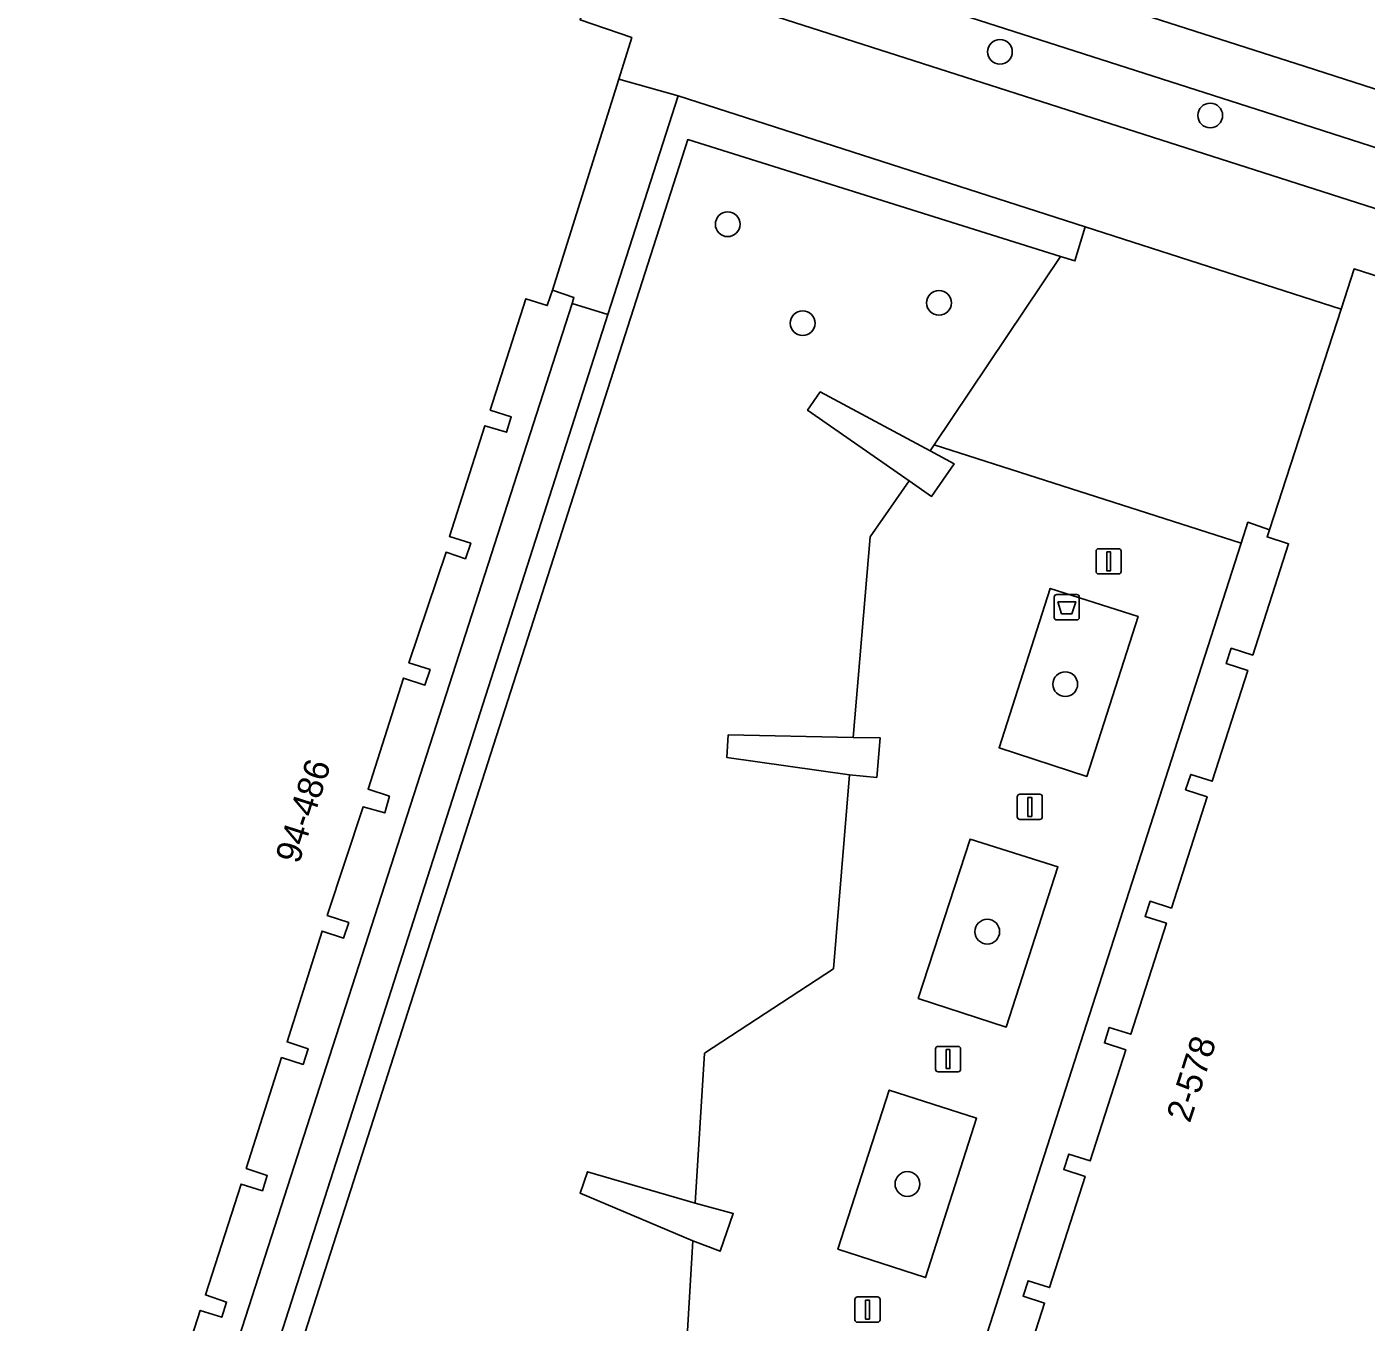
# Model space of a CAD drawing. Extents: x 160675 to 161153, y 383241 to 383714.
# Drawn here: x 160887.3 to 160940.2, y 383336.8 to 383388 of the extents above; entities that cross this region are included whole.
import ezdxf

# ---------------------------------------------------------------- set-up
doc = ezdxf.new("R2010")
doc.units = 0
for name, color, linetype in [('IMGEO_Afvalbak', 7, 'Continuous'), ('IMGEO_Boom', 7, 'Continuous'), ('IMGEO_Erf', 7, 'Continuous'), ('IMGEO_Groenvoorziening', 7, 'Continuous'), ('IMGEO_Haag', 7, 'Continuous'), ('IMGEO_Lichtmast', 7, 'Continuous'), ('IMGEO_Muur', 7, 'Continuous'), ('IMGEO_Pand', 7, 'Continuous'), ('IMGEO_Pand_nummerreeks', 7, 'Continuous'), ('IMGEO_Parkeervlak_open', 7, 'Continuous'), ('IMGEO_Rijbaan_lokaal_open', 7, 'Continuous'), ('IMGEO_Voetpad_op_trap', 7, 'Continuous'), ('IMGEO_Voetpad_open', 7, 'Continuous')]:
    doc.layers.add(name, color=color, linetype=linetype)

msp = doc.modelspace()

# ---------------------------------------------------------------- linework, layer by layer
at = {"layer": 'IMGEO_Afvalbak'}
for p, q in [((160927.888, 383364.641), (160927.888, 383365.441)), ((160927.888, 383365.441), (160927.888, 383364.641)), ((160927.988, 383365.541), (160928.778, 383365.541)), ((160928.778, 383365.541), (160927.988, 383365.541)), ((160928.878, 383365.441), (160928.878, 383364.641)), ((160928.878, 383364.641), (160928.878, 383365.441)), ((160928.778, 383364.541), (160927.988, 383364.541)), ((160927.988, 383364.541), (160928.778, 383364.541))]:
    msp.add_line(p, q, dxfattribs=at)
msp.add_lwpolyline([(160928.031, 383365.255), (160928.735, 383365.255), (160928.586, 383364.785), (160928.18, 383364.785), (160928.031, 383365.255)], dxfattribs=at)
for centre, start, end in [((160927.988, 383365.441), 90, 180), ((160927.988, 383365.441), 90, 180), ((160928.778, 383365.441), 0, 90), ((160928.778, 383365.441), 360, 90), ((160927.988, 383364.641), 180, 270), ((160927.988, 383364.641), 180, 270), ((160928.778, 383364.641), 270, 0), ((160928.778, 383364.641), 270, 0)]:
    msp.add_arc(centre, 0.1, start, end, dxfattribs=at)
at = {"layer": 'IMGEO_Boom'}
for centre in [(160925.742, 383386.991), (160934.054, 383384.475), (160914.982, 383380.178), (160923.332, 383377.07), (160917.945, 383376.267), (160928.323, 383362), (160925.24, 383352.219), (160922.085, 383342.246)]:
    msp.add_circle(centre, 0.489, dxfattribs=at)
at = {"layer": 'IMGEO_Erf'}
for points in [[(160892.596, 383326.678), (160908.829, 383377.047), (160908.904, 383377.281), (160908.053, 383377.576), (160907.965, 383377.311), (160907.849, 383376.964), (160907.007, 383377.234), (160905.595, 383372.835), (160906.425, 383372.571), (160906.239, 383371.958), (160905.387, 383372.216), (160903.983, 383367.839), (160904.826, 383367.572), (160904.615, 383366.955), (160903.846, 383367.212), (160902.377, 383362.846), (160903.214, 383362.579), (160903.015, 383361.964), (160902.168, 383362.238), (160900.763, 383357.851), (160901.606, 383357.571), (160901.425, 383356.911), (160900.567, 383357.147), (160899.154, 383352.863), (160900, 383352.578), (160899.795, 383351.963), (160898.951, 383352.244), (160897.562, 383347.859), (160898.393, 383347.591), (160898.195, 383346.974), (160897.348, 383347.245), (160895.95, 383342.861), (160896.781, 383342.582), (160896.592, 383341.977), (160895.743, 383342.243), (160894.335, 383337.863), (160895.175, 383337.583), (160894.983, 383336.978), (160894.135, 383337.248), (160892.722, 383332.86)], [(160926.093, 383333.155), (160927.504, 383337.542), (160926.656, 383337.813), (160926.853, 383338.425), (160927.701, 383338.154), (160929.11, 383342.548), (160928.262, 383342.819), (160928.458, 383343.427), (160929.306, 383343.156), (160930.717, 383347.554), (160929.869, 383347.825), (160930.064, 383348.435), (160930.912, 383348.164), (160932.324, 383352.55), (160931.476, 383352.821), (160931.674, 383353.424), (160932.522, 383353.153), (160933.93, 383357.554), (160933.082, 383357.825), (160933.282, 383358.432), (160934.13, 383358.161), (160935.536, 383362.541), (160934.688, 383362.812), (160934.884, 383363.422), (160935.732, 383363.151), (160937.149, 383367.552), (160936.301, 383367.823), (160936.399, 383368.105), (160935.542, 383368.4), (160935.274, 383367.567), (160919.362, 383318.078)]]:
    msp.add_lwpolyline(points, dxfattribs=at)
at = {"layer": 'IMGEO_Groenvoorziening'}
for points in [[(160936.244, 383384.606), (160905.032, 383394.612), (160904.349, 383392.464), (160906.167, 383391.864), (160909.89, 383390.636), (160942.548, 383380.163), (160946.319, 383378.951), (160951.574, 383377.261), (160951.67, 383377.543), (160952.13, 383379.495)], [(160929.17, 383358.356), (160931.204, 383364.676), (160927.731, 383365.787), (160925.705, 383359.49)], [(160925.983, 383348.446), (160928.031, 383354.781), (160924.562, 383355.873), (160922.515, 383349.581)], [(160924.82, 383344.845), (160921.365, 383345.957), (160919.339, 383339.675), (160922.799, 383338.551)]]:
    msp.add_lwpolyline(points, close=True, dxfattribs=at)
msp.add_lwpolyline([(160913.099, 383331.561), (160913.607, 383340), (160909.149, 383341.881), (160909.437, 383342.731), (160913.693, 383341.495), (160914.069, 383347.413), (160919.158, 383350.753), (160919.792, 383358.422), (160914.941, 383359.108), (160915.004, 383359.993), (160919.936, 383359.895), (160920.611, 383367.817), (160922.152, 383370.034), (160918.137, 383372.825), (160918.639, 383373.548), (160922.977, 383371.221), (160923.146, 383371.464), (160928.13, 383378.906), (160913.402, 383383.521), (160895.217, 383326.869)], dxfattribs=at)
at = {"layer": 'IMGEO_Haag'}
for points in [[(160905.032, 383394.612), (160904.349, 383392.464), (160906.167, 383391.864), (160909.89, 383390.636), (160942.548, 383380.163), (160946.319, 383378.951), (160951.574, 383377.261), (160951.67, 383377.543), (160952.13, 383379.495), (160936.244, 383384.606)], [(160929.17, 383358.356), (160931.204, 383364.676), (160927.731, 383365.787), (160925.705, 383359.49)], [(160925.983, 383348.446), (160928.031, 383354.781), (160924.562, 383355.873), (160922.515, 383349.581)], [(160924.82, 383344.845), (160921.365, 383345.957), (160919.339, 383339.675), (160922.799, 383338.551)]]:
    msp.add_lwpolyline(points, close=True, dxfattribs=at)
at = {"layer": 'IMGEO_Lichtmast'}
for p, q in [((160929.542, 383366.455), (160929.542, 383367.255)), ((160929.542, 383367.255), (160929.542, 383366.455)), ((160929.642, 383367.355), (160930.432, 383367.355)), ((160930.432, 383367.355), (160929.642, 383367.355)), ((160930.532, 383367.255), (160930.532, 383366.455)), ((160930.532, 383366.455), (160930.532, 383367.255)), ((160930.432, 383366.355), (160929.642, 383366.355)), ((160929.642, 383366.355), (160930.432, 383366.355)), ((160926.427, 383356.751), (160926.427, 383357.551)), ((160926.427, 383357.551), (160926.427, 383356.751)), ((160926.527, 383357.651), (160927.317, 383357.651)), ((160927.317, 383357.651), (160926.527, 383357.651)), ((160927.417, 383357.551), (160927.417, 383356.751)), ((160927.417, 383356.751), (160927.417, 383357.551)), ((160927.317, 383356.651), (160926.527, 383356.651)), ((160926.527, 383356.651), (160927.317, 383356.651)), ((160923.296, 383347.683), (160924.086, 383347.683)), ((160924.086, 383347.683), (160923.296, 383347.683)), ((160923.196, 383346.783), (160923.196, 383347.583)), ((160923.196, 383347.583), (160923.196, 383346.783)), ((160924.186, 383347.583), (160924.186, 383346.783)), ((160924.186, 383346.783), (160924.186, 383347.583)), ((160924.086, 383346.683), (160923.296, 383346.683)), ((160923.296, 383346.683), (160924.086, 383346.683)), ((160920.012, 383336.884), (160920.012, 383337.684)), ((160920.012, 383337.684), (160920.012, 383336.884)), ((160920.112, 383337.784), (160920.902, 383337.784)), ((160920.902, 383337.784), (160920.112, 383337.784)), ((160921.002, 383337.684), (160921.002, 383336.884)), ((160921.002, 383336.884), (160921.002, 383337.684)), ((160920.902, 383336.784), (160920.112, 383336.784)), ((160920.112, 383336.784), (160920.902, 383336.784))]:
    msp.add_line(p, q, dxfattribs=at)
for points in [[(160929.962, 383367.23), (160930.112, 383367.23), (160930.112, 383366.48), (160929.962, 383366.48), (160929.962, 383367.23)], [(160926.847, 383357.526), (160926.997, 383357.526), (160926.997, 383356.776), (160926.847, 383356.776), (160926.847, 383357.526)], [(160923.616, 383347.558), (160923.766, 383347.558), (160923.766, 383346.808), (160923.616, 383346.808), (160923.616, 383347.558)], [(160920.432, 383337.659), (160920.582, 383337.659), (160920.582, 383336.909), (160920.432, 383336.909), (160920.432, 383337.659)]]:
    msp.add_lwpolyline(points, dxfattribs=at)
for centre, start, end in [((160929.642, 383367.255), 90, 180), ((160929.642, 383367.255), 90, 180), ((160930.432, 383367.255), 0, 90), ((160930.432, 383367.255), 360, 90), ((160929.642, 383366.455), 180, 270), ((160929.642, 383366.455), 180, 270), ((160930.432, 383366.455), 270, 0), ((160930.432, 383366.455), 270, 0), ((160926.527, 383357.551), 90, 180), ((160926.527, 383357.551), 90, 180), ((160927.317, 383357.551), 0, 90), ((160927.317, 383357.551), 360, 90), ((160926.527, 383356.751), 180, 270), ((160926.527, 383356.751), 180, 270), ((160927.317, 383356.751), 270, 0), ((160927.317, 383356.751), 270, 0), ((160923.296, 383347.583), 90, 180), ((160923.296, 383347.583), 90, 180), ((160924.086, 383347.583), 0, 90), ((160924.086, 383347.583), 360, 90), ((160923.296, 383346.783), 180, 270), ((160923.296, 383346.783), 180, 270), ((160924.086, 383346.783), 270, 0), ((160924.086, 383346.783), 270, 0), ((160920.112, 383337.684), 90, 180), ((160920.112, 383337.684), 90, 180), ((160920.902, 383337.684), 0, 90), ((160920.902, 383337.684), 360, 90), ((160920.112, 383336.884), 180, 270), ((160920.112, 383336.884), 180, 270), ((160920.902, 383336.884), 270, 0), ((160920.902, 383336.884), 270, 0)]:
    msp.add_arc(centre, 0.1, start, end, dxfattribs=at)
at = {"layer": 'IMGEO_Muur'}
msp.add_lwpolyline([(160907.337, 383322.987), (160906.197, 383323.352), (160895.217, 383326.869), (160913.402, 383383.521), (160928.13, 383378.906), (160928.705, 383378.726), (160929.108, 383380.073), (160913.017, 383385.246), (160910.248, 383376.612), (160894.112, 383326.296), (160907.057, 383322.147)], close=True, dxfattribs=at)
for points in [[(160908.829, 383377.047), (160908.904, 383377.281), (160908.053, 383377.576)], [(160891.752, 383326.936), (160892.596, 383326.678), (160908.829, 383377.047)], [(160936.399, 383368.105), (160935.542, 383368.4), (160935.274, 383367.567)], [(160935.274, 383367.567), (160919.362, 383318.078), (160920.218, 383317.803)]]:
    msp.add_lwpolyline(points, dxfattribs=at)
at = {"layer": 'IMGEO_Pand'}
for points in [[(160892.722, 383332.86), (160894.135, 383337.248), (160894.983, 383336.978), (160895.175, 383337.583), (160894.335, 383337.863), (160895.743, 383342.243), (160896.592, 383341.977), (160896.781, 383342.582), (160895.95, 383342.861), (160897.348, 383347.245), (160898.195, 383346.974), (160898.393, 383347.591), (160897.562, 383347.859), (160898.951, 383352.244), (160899.795, 383351.963), (160900, 383352.578), (160899.154, 383352.863), (160900.567, 383357.147), (160901.425, 383356.911), (160901.606, 383357.571), (160900.763, 383357.851), (160902.168, 383362.238), (160903.015, 383361.964), (160903.214, 383362.579), (160902.377, 383362.846), (160903.846, 383367.212), (160904.615, 383366.955), (160904.826, 383367.572), (160903.983, 383367.839), (160905.387, 383372.216), (160906.239, 383371.958), (160906.425, 383372.571), (160905.595, 383372.835), (160907.007, 383377.234), (160907.849, 383376.964), (160907.965, 383377.311), (160908.053, 383377.576), (160910.671, 383385.909), (160911.188, 383387.556), (160909.143, 383388.26)], [(160941.762, 383377.775), (160939.741, 383378.41), (160939.225, 383376.82), (160936.399, 383368.105), (160936.301, 383367.823), (160937.149, 383367.552), (160935.732, 383363.151), (160934.884, 383363.422), (160934.688, 383362.812), (160935.536, 383362.541), (160934.13, 383358.161), (160933.282, 383358.432), (160933.082, 383357.825), (160933.93, 383357.554), (160932.522, 383353.153), (160931.674, 383353.424), (160931.476, 383352.821), (160932.324, 383352.55), (160930.912, 383348.164), (160930.064, 383348.435), (160929.869, 383347.825), (160930.717, 383347.554), (160929.306, 383343.156), (160928.458, 383343.427), (160928.262, 383342.819), (160929.11, 383342.548), (160927.701, 383338.154), (160926.853, 383338.425), (160926.656, 383337.813), (160927.504, 383337.542), (160926.093, 383333.155)]]:
    msp.add_lwpolyline(points, dxfattribs=at)
at = {"layer": 'IMGEO_Parkeervlak_open'}
msp.add_lwpolyline([(160953.275, 383381.428), (160937.803, 383386.409), (160902.588, 383397.698), (160901.917, 383395.611), (160905.032, 383394.612), (160936.244, 383384.606), (160952.13, 383379.495), (160952.654, 383381.092)], dxfattribs=at)
at = {"layer": 'IMGEO_Rijbaan_lokaal_open'}
msp.add_lwpolyline([(160870.773, 383407.909), (160899.445, 383398.723), (160902.588, 383397.698), (160937.803, 383386.409), (160953.275, 383381.428), (160955.527, 383379.454), (160957.362, 383377.84), (160957.988, 383377.643), (160975.522, 383372.116), (160978.404, 383371.21), (160983.568, 383369.569)], dxfattribs=at)
at = {"layer": 'IMGEO_Voetpad_op_trap'}
for points in [[(160913.017, 383385.246), (160910.671, 383385.909), (160908.053, 383377.576), (160908.904, 383377.281), (160908.829, 383377.047), (160910.248, 383376.612)], [(160939.225, 383376.82), (160929.108, 383380.073), (160928.705, 383378.726), (160928.13, 383378.906), (160923.146, 383371.464), (160935.274, 383367.567), (160935.542, 383368.4), (160936.399, 383368.105)]]:
    msp.add_lwpolyline(points, close=True, dxfattribs=at)
at = {"layer": 'IMGEO_Voetpad_open'}
for points in [[(160909.89, 383390.636), (160909.143, 383388.26), (160911.188, 383387.556), (160910.671, 383385.909), (160913.017, 383385.246), (160929.108, 383380.073), (160939.225, 383376.82), (160939.741, 383378.41), (160941.762, 383377.775), (160942.548, 383380.163)], [(160910.248, 383376.612), (160908.829, 383377.047), (160892.596, 383326.678), (160894.112, 383326.296)], [(160922.152, 383370.034), (160923.039, 383369.418), (160923.935, 383370.707), (160922.977, 383371.221), (160918.639, 383373.548), (160918.137, 383372.825)], [(160927.731, 383365.787), (160931.204, 383364.676), (160929.17, 383358.356), (160925.705, 383359.49)], [(160919.792, 383358.422), (160920.874, 383358.316), (160921.003, 383359.884), (160919.936, 383359.895), (160915.004, 383359.993), (160914.941, 383359.108)], [(160922.515, 383349.581), (160924.562, 383355.873), (160928.031, 383354.781), (160925.983, 383348.446)], [(160919.339, 383339.675), (160921.365, 383345.957), (160924.82, 383344.845), (160922.799, 383338.551)], [(160913.693, 383341.495), (160909.437, 383342.731), (160909.149, 383341.881), (160913.607, 383340), (160914.679, 383339.59), (160915.201, 383341.078)]]:
    msp.add_lwpolyline(points, close=True, dxfattribs=at)
msp.add_lwpolyline([(160919.362, 383318.078), (160935.274, 383367.567), (160923.146, 383371.464), (160922.977, 383371.221), (160923.935, 383370.707), (160923.039, 383369.418), (160922.152, 383370.034), (160920.611, 383367.817), (160919.936, 383359.895), (160921.003, 383359.884), (160920.874, 383358.316), (160919.792, 383358.422), (160919.158, 383350.753), (160914.069, 383347.413), (160913.693, 383341.495), (160915.201, 383341.078), (160914.679, 383339.59), (160913.607, 383340), (160913.099, 383331.561)], dxfattribs=at)

# ---------------------------------------------------------------- texts
at = {"layer": 'IMGEO_Pand_nummerreeks'}
for s, rotation, p in [('94-486', 72.1788, (160898.03, 383354.861)), ('2-578', 72.0208, (160933.249, 383344.627))]:
    msp.add_text(s, height=1, rotation=rotation, dxfattribs=at).set_placement(p)

doc.saveas('drawing.dxf')
